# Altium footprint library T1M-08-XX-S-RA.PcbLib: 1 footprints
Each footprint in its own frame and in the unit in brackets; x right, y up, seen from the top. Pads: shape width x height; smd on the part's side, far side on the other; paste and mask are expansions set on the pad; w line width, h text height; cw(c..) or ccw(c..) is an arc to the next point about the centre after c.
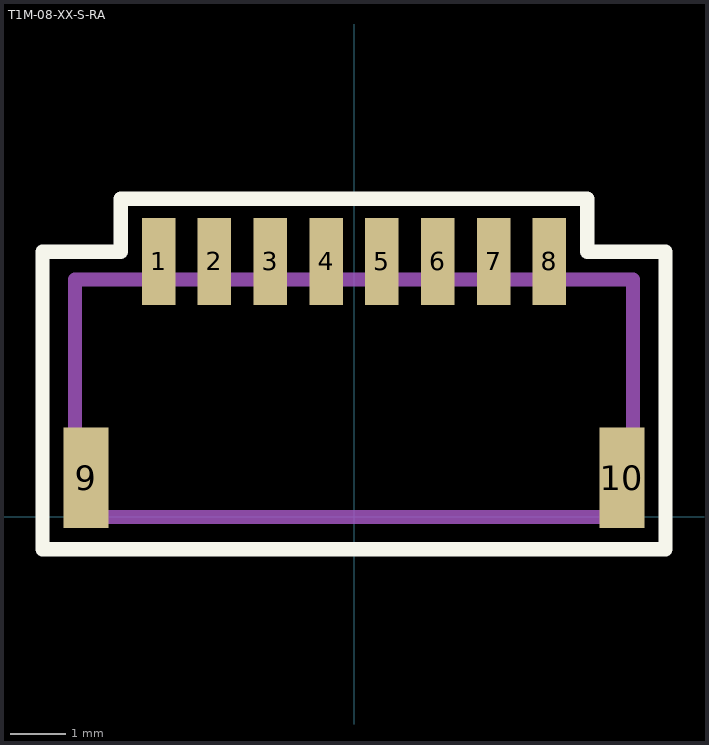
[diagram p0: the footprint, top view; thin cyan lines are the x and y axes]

## T1M-08-XX-S-RA [mm]
pads (10):
  rect 0.6x1.55 smd mask+0.05: 1(-3.5,4.575) 2(-2.5,4.575) 3(-1.5,4.575) 4(-0.5,4.575) 5(0.5,4.575) 6(1.5,4.575) 7(2.5,4.575) 8(3.5,4.575)
  rect 0.8x1.8 smd mask+0.05: 9(-4.8,0.7) 10(4.8,0.7)
Top Overlay:
  lines w0.254: -5.58,-0.581 5.58,-0.581 5.58,4.75 4.18,4.75 4.18,5.7 -4.18,5.7 -4.18,4.75 -5.58,4.75 -5.58,-0.581
Mechanical 1:
  lines w0.254: -5,0 5,0 5,4.25 -5,4.25 -5,0
  text "J1" at -0.446,2.043 h0.76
